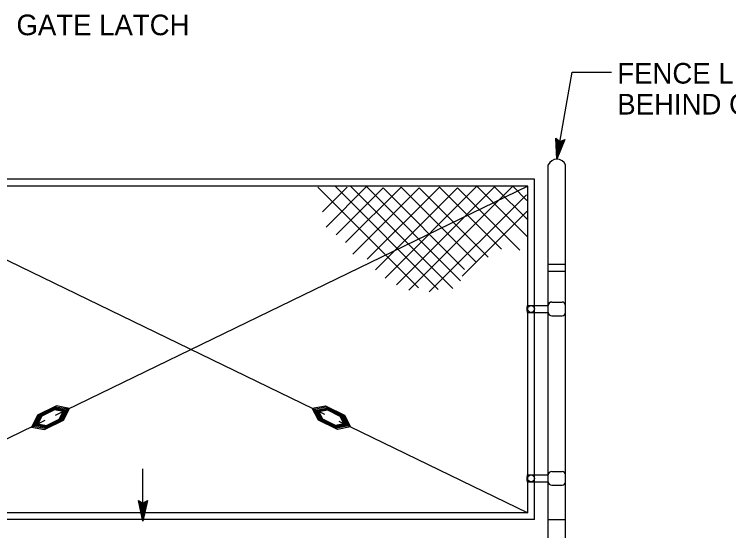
# Model space of a CAD drawing. Extents: x -121933 to -117742, y -103160 to -100084.
# Drawn here: x -120965.9 to -120757.9, y -102378.5 to -102228.3 of the extents above; entities that cross this region are included whole.
import ezdxf

# ---------------------------------------------------------------- set-up
doc = ezdxf.new("R2010")
doc.units = 0
for name, color, linetype in [('G-MARK', 7, 'Continuous'), ('G-TEXT', 7, 'Continuous'), ('Misc CnstDet(22)', 7, 'Continuous'), ('Nongeo Data(60)', 7, 'Continuous')]:
    doc.layers.add(name, color=color, linetype=linetype)

msp = doc.modelspace()

# ---------------------------------------------------------------- linework, layer by layer
at = {"layer": 'G-MARK'}
for p, q in [((-120803.49, -102245.1), (-120791.99, -102245.1)), ((-120807.89, -102270.41), (-120808.17, -102264.27)), ((-120808.17, -102264.27), (-120808.17, -102264.27)), ((-120808.17, -102264.27), (-120807, -102265.28)), ((-120805.54, -102264.72), (-120807.89, -102270.41)), ((-120807.65, -102269.03), (-120807.86, -102264.56)), ((-120805.93, -102264.88), (-120807.65, -102269.05)), ((-120807.41, -102267.68), (-120807.55, -102264.79)), ((-120806.32, -102265.04), (-120807.41, -102267.68)), ((-120807.17, -102266.32), (-120807.23, -102265.09)), ((-120807, -102265.28), (-120805.54, -102264.72)), ((-120805.54, -102264.72), (-120805.54, -102264.72)), ((-120806.69, -102265.16), (-120807.17, -102266.32)), ((-120807.89, -102270.41), (-120807.89, -102270.41)), ((-120928.4, -102375.7), (-120928.4, -102360.47))]:
    msp.add_line(p, q, dxfattribs=at)
msp.add_lwpolyline([(-120807.89, -102270.41), (-120803.49, -102245.1), (-120803.49, -102245.1)], dxfattribs=at)
at = {"layer": 'G-TEXT'}
for p, q in [((-120928.4, -102375.7), (-120929.73, -102369.7)), ((-120929.73, -102369.7), (-120929.73, -102369.7)), ((-120929.73, -102369.7), (-120928.4, -102370.5)), ((-120928.4, -102374.31), (-120929.37, -102369.93)), ((-120928.4, -102372.94), (-120929.02, -102370.11)), ((-120928.4, -102371.55), (-120928.66, -102370.35)), ((-120928.4, -102370.5), (-120927.06, -102369.7)), ((-120927.06, -102369.7), (-120928.4, -102375.7)), ((-120927.42, -102369.92), (-120928.4, -102374.32)), ((-120927.77, -102370.15), (-120928.4, -102372.94)), ((-120928.12, -102370.33), (-120928.4, -102371.55)), ((-120927.06, -102369.7), (-120927.06, -102369.7)), ((-120928.4, -102375.7), (-120928.4, -102375.7))]:
    msp.add_line(p, q, dxfattribs=at)
at = {"layer": 'Nongeo Data(60)'}
for p, q in [((-120810.39, -102358.97), (-120810.39, -102272.05)), ((-120805.39, -102358.97), (-120805.39, -102272.05)), ((-120814.39, -102276.24), (-121014.39, -102276.24)), ((-120814.39, -102301.58), (-120814.39, -102276.24)), ((-120816.39, -102278.24), (-121012.39, -102278.24)), ((-121012.39, -102278.24), (-120875.51, -102344.59)), ((-120816.39, -102278.24), (-120953.95, -102344.92)), ((-120848.15, -102307.83), (-120877.46, -102278.52)), ((-120876.15, -102285.75), (-120868.91, -102278.52)), ((-120875.08, -102290.14), (-120863.22, -102278.28)), ((-120842.45, -102308.3), (-120872.47, -102278.28)), ((-120872.12, -102292.4), (-120858.47, -102278.75)), ((-120869.39, -102294.65), (-120853.25, -102278.52)), ((-120838.18, -102308.06), (-120867.96, -102278.28)), ((-120867.25, -102297.98), (-120848.03, -102278.75)), ((-120835.92, -102305.81), (-120863.45, -102278.28)), ((-120863.1, -102299.52), (-120842.09, -102278.52)), ((-120860.72, -102302.6), (-120836.87, -102278.75)), ((-120834.74, -102302.49), (-120858.47, -102278.75)), ((-120857.88, -102304.98), (-120831.18, -102278.28)), ((-120854.54, -102306.91), (-120825.79, -102278.16)), ((-120831.53, -102300.23), (-120853.25, -102278.52)), ((-120850.99, -102308.54), (-120820.73, -102278.28)), ((-120827.85, -102298.93), (-120848.03, -102278.75)), ((-120824.06, -102296.55), (-120842.09, -102278.52)), ((-120818.72, -102296.91), (-120836.87, -102278.75)), ((-120816.52, -102292.93), (-120831.18, -102278.28)), ((-120816.39, -102288.08), (-120825.95, -102278.52)), ((-120816.63, -102282.38), (-120820.73, -102278.28)), ((-120816.39, -102301.21), (-120816.39, -102278.24)), ((-120845.06, -102309.01), (-120816.78, -102280.74)), ((-120835.45, -102304.38), (-120816.59, -102285.53)), ((-120816.39, -102373.24), (-120816.39, -102301.21)), ((-120814.39, -102375.24), (-120814.39, -102301.58)), ((-120810.39, -102300.95), (-120805.39, -102300.95)), ((-120810.39, -102302.95), (-120805.39, -102302.95)), ((-120814.39, -102312.95), (-120814.39, -102309.67)), ((-120810.39, -102311.93), (-120810.39, -102309.67)), ((-120805.39, -102311.94), (-120805.39, -102309.67)), ((-120810.39, -102317.59), (-120810.39, -102311.93)), ((-120809.39, -102311.95), (-120806.39, -102311.95)), ((-120805.39, -102317.59), (-120805.39, -102311.9)), ((-120816.51, -102312.95), (-120810.39, -102312.95)), ((-120816.51, -102314.95), (-120810.39, -102314.95)), ((-120814.39, -102317.59), (-120814.39, -102314.95)), ((-120810.39, -102314.95), (-120810.39, -102312.95)), ((-120805.39, -102314.95), (-120805.39, -102312.95)), ((-120809.39, -102315.95), (-120806.39, -102315.95)), ((-120953.54, -102342.16), (-120959.11, -102344.87)), ((-120953.72, -102342.51), (-120958.74, -102344.94)), ((-120953.88, -102342.82), (-120958.39, -102345.01)), ((-120954.02, -102343.09), (-120958.09, -102345.07)), ((-120954.16, -102343.35), (-120957.81, -102345.12)), ((-120951.66, -102343.82), (-120954.16, -102343.35)), ((-120951.26, -102343.62), (-120954.02, -102343.09)), ((-120950.8, -102343.4), (-120953.88, -102342.82)), ((-120950.3, -102343.16), (-120953.72, -102342.51)), ((-120949.74, -102342.89), (-120953.54, -102342.16)), ((-120952.83, -102346.07), (-120951.66, -102343.82)), ((-120952.55, -102346.12), (-120951.26, -102343.62)), ((-120952.24, -102346.18), (-120950.8, -102343.4)), ((-120951.9, -102346.25), (-120950.3, -102343.16)), ((-120951.52, -102346.32), (-120949.74, -102342.89)), ((-120879.1, -102342.86), (-120875.3, -102342.13)), ((-120877.33, -102346.29), (-120879.1, -102342.86)), ((-120878.54, -102343.14), (-120875.13, -102342.48)), ((-120876.95, -102346.23), (-120878.54, -102343.14)), ((-120878.04, -102343.38), (-120874.97, -102342.8)), ((-120876.6, -102346.17), (-120878.04, -102343.38)), ((-120877.59, -102343.61), (-120874.82, -102343.08)), ((-120876.3, -102346.11), (-120877.59, -102343.61)), ((-120877.18, -102343.81), (-120874.69, -102343.34)), ((-120876.02, -102346.06), (-120877.18, -102343.81)), ((-120875.3, -102342.13), (-120869.73, -102344.85)), ((-120875.13, -102342.48), (-120870.11, -102344.92)), ((-120874.97, -102342.8), (-120870.45, -102344.99)), ((-120874.82, -102343.08), (-120870.76, -102345.06)), ((-120874.69, -102343.34), (-120871.04, -102345.11)), ((-120959.11, -102344.87), (-120960.89, -102348.31)), ((-120958.74, -102344.94), (-120960.33, -102348.04)), ((-120958.39, -102345.01), (-120959.83, -102347.79)), ((-120958.09, -102345.07), (-120959.38, -102347.57)), ((-120957.81, -102345.12), (-120958.98, -102347.38)), ((-120956.76, -102348.38), (-120952.24, -102346.18)), ((-120956.62, -102348.1), (-120952.55, -102346.12)), ((-120956.49, -102347.85), (-120952.83, -102346.07)), ((-120872.09, -102348.36), (-120876.6, -102346.17)), ((-120872.23, -102348.09), (-120876.3, -102346.11)), ((-120872.36, -102347.84), (-120876.02, -102346.06)), ((-120871.04, -102345.11), (-120869.87, -102347.37)), ((-120870.76, -102345.06), (-120869.46, -102347.56)), ((-120870.45, -102344.99), (-120869.01, -102347.78)), ((-120870.11, -102344.92), (-120868.51, -102348.01)), ((-120869.73, -102344.85), (-120867.95, -102348.28)), ((-120956.97, -102346.39), (-121012.39, -102373.24)), ((-120960.33, -102348.04), (-120956.92, -102348.69)), ((-120959.83, -102347.79), (-120956.76, -102348.38)), ((-120959.38, -102347.57), (-120956.62, -102348.1)), ((-120958.98, -102347.38), (-120956.49, -102347.85)), ((-120957.09, -102349.03), (-120951.52, -102346.32)), ((-120956.92, -102348.69), (-120951.9, -102346.25)), ((-120871.75, -102349), (-120877.33, -102346.29)), ((-120871.93, -102348.66), (-120876.95, -102346.23)), ((-120869.87, -102347.37), (-120872.36, -102347.84)), ((-120869.46, -102347.56), (-120872.23, -102348.09)), ((-120869.01, -102347.78), (-120872.09, -102348.36)), ((-120868.51, -102348.01), (-120871.93, -102348.66)), ((-120867.95, -102348.28), (-120871.75, -102349)), ((-120871.34, -102346.61), (-120816.39, -102373.24)), ((-120960.89, -102348.31), (-120957.09, -102349.03)), ((-120810.39, -102361.22), (-120810.39, -102358.97)), ((-120810.39, -102366.89), (-120810.39, -102358.97)), ((-120805.39, -102361.24), (-120805.39, -102358.97)), ((-120805.39, -102366.89), (-120805.39, -102358.97)), ((-120816.51, -102362.24), (-120810.5, -102362.24)), ((-120810.39, -102366.89), (-120810.39, -102361.22)), ((-120810.39, -102364.24), (-120810.39, -102362.24)), ((-120809.39, -102361.24), (-120806.39, -102361.24)), ((-120805.39, -102366.89), (-120805.39, -102361.19)), ((-120805.39, -102364.24), (-120805.39, -102362.24)), ((-120816.51, -102364.24), (-120810.39, -102364.24)), ((-120810.39, -102426.24), (-120810.39, -102366.89)), ((-120809.39, -102365.24), (-120806.39, -102365.24)), ((-120805.39, -102426.24), (-120805.39, -102366.89)), ((-120816.39, -102373.24), (-121012.39, -102373.24)), ((-120814.39, -102375.24), (-121014.39, -102375.24)), ((-120810.39, -102375.24), (-120805.39, -102375.24))]:
    msp.add_line(p, q, dxfattribs=at)
for centre in [(-120815.38, -102313.95), (-120815.39, -102363.24)]:
    msp.add_circle(centre, 1, dxfattribs=at)
for centre, radius, start, end in [((-120807.89, -102273.13), 2.72, 23.2888, 156.7112), ((-120809.39, -102312.95), 1, 90, 180), ((-120806.39, -102312.95), 1, 0, 90), ((-120809.39, -102314.95), 1, 180, 270), ((-120806.39, -102314.95), 1, 270, 0), ((-120809.39, -102362.24), 1, 90, 180), ((-120806.39, -102362.24), 1, 0, 90), ((-120809.39, -102364.24), 1, 180, 270), ((-120806.39, -102364.24), 1, 270, 0)]:
    msp.add_arc(centre, radius, start, end, dxfattribs=at)
for centre in [(-120816.51, -102313.95), (-120816.51, -102363.24)]:
    msp.add_ellipse(centre, major_axis=(0, -1), ratio=0.098201, start_param=3.141593, end_param=6.283185, dxfattribs=at)

# ---------------------------------------------------------------- texts
at = {"layer": 'Misc CnstDet(22)'}
for s, p in [('GATE LATCH', (-120965.22, -102234.34)), ('FENCE LINE EXTENDS', (-120790.31, -102248.41)), ('BEHIND GATE POST', (-120790.31, -102257.41))]:
    msp.add_text(s, height=6, dxfattribs=at).set_placement(p)

doc.saveas('drawing.dxf')
